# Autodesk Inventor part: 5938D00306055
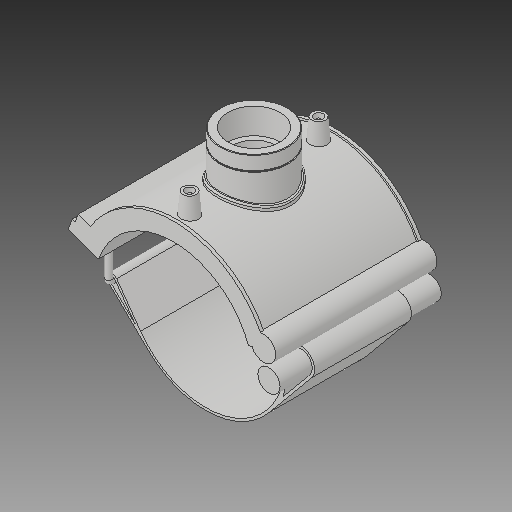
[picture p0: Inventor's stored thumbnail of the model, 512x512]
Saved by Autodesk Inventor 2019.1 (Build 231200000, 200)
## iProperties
Created: 2017-07
Part Number: 5938D00306055
Material: Generic
Description: PLASSON TRANSITION SADDLE 6''DIPS x 2"NPT
Document SubType Name: Modeling
Designer: KIM
Density: 1 g/cm^3
Appearance: Default
Author: KIM
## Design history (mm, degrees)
derived "5938D.ipt"
feature "Solid1::5938D.ipt"
tag "TaggingFeature1"
body "Solid1"
other parameters: "d0" = 174.5, "d1" = 209.4, "d2" = 441.96, "d3" = 43.625, "d4" = 176.022, "d5" = 0, "d40" = 108.888, "d41" = 79.3184, "d43" = 0, "d45" = 0, "d47" = 151.436, "d48" = 73.6528, "d50" = 0, "d78" = 126.7, "d79" = 15, "d80" = 70.4088, "d82" = 5 deg, "d84" = 4, "d85" = 14, "d86" = 0, "d87" = 3, "d88" = 0, "d96" = 213.588, "d97" = 3.52044, "d98" = 0, "d102" = 1.69968, "d103" = 56.656, "d104" = 28.0416, "d105" = 0, "d106" = 45.3248, "d108" = 0, "d109" = -15.57867, "d111" = 0.5, "d112" = 0.5, "d113" = 0, "d114" = 0.5, "d117" = 0.56656, "d120" = 140 deg, "d121" = 24.228, "d122" = 20 deg, "d123" = 837.6, "d124" = 125.64, "d126" = 0, "d143" = 179.735, "d145" = 26.84615, "d149" = 2.6175, "d150" = 29.53077, "d153" = 176.022, "d154" = 0, "d156" = 104.7, "d157" = 160 deg, "d159" = 6.98, "d161" = 2.6175, "d162" = 105.6132, "d163" = 0, "d164" = 87.25, "d167" = 17.45, "d168" = 102.14634, "d170" = 2.6175, "d172" = 0, "d173" = 1, "d175" = 87.25, "d176" = 20 deg, "d177" = 12.215, "d178" = 34.9, "d180" = 0, "d183" = 13.96, "d184" = 9.772, "d185" = 57.20715, "d186" = 57.20715, "d187" = 104.7, "d188" = 10.47, "d189" = 12.215, "d190" = 0, "d191" = 125.64, "d193" = 6.98, "d194" = 3.57725, "d195" = 90 deg, "d197" = 0, "d199" = 0, "d_" = 174.5, "B_" = 176.784, "H_" = 46.736, "L_" = 176.022, "d_t" = 6, "G_" = 56.656, "d148" = 2.6175, "d160" = 2.6175, "d169" = 2.6175, "d192" = 6.98
